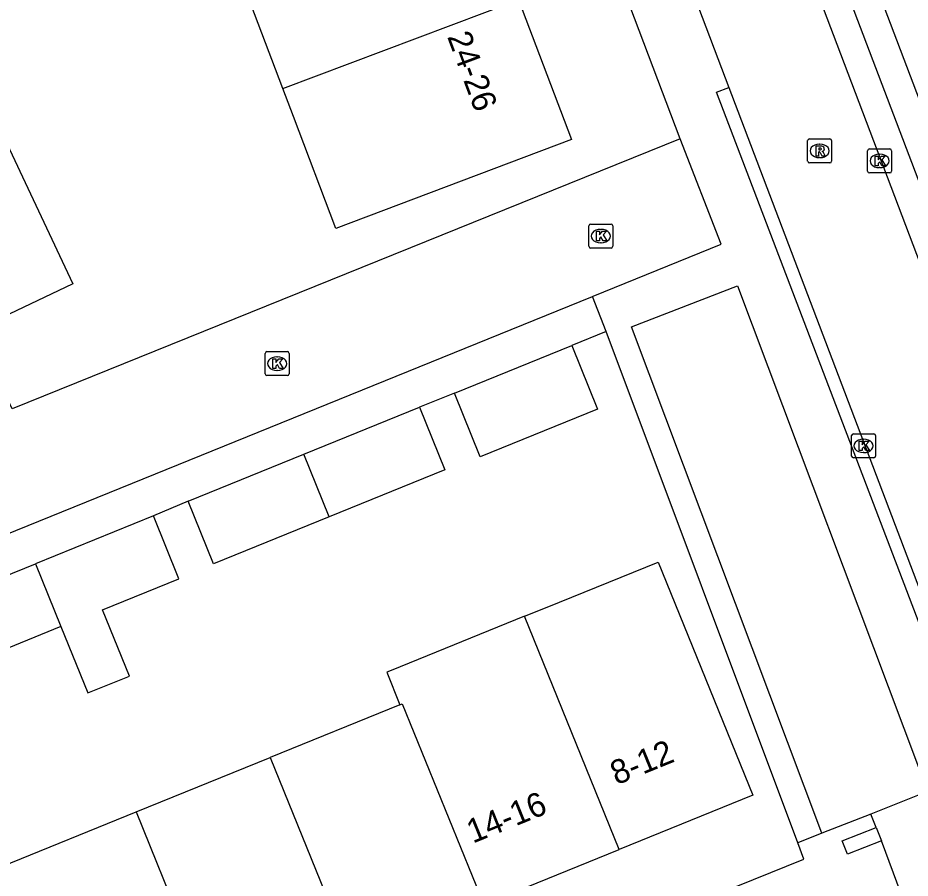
# Model space of a CAD drawing. Extents: x 162990 to 165007, y 383433 to 384336.
# Drawn here: x 163902.75 to 163939.97, y 384004.56 to 384040.43 of the extents above; entities that cross this region are included whole.
import ezdxf

# ---------------------------------------------------------------- set-up
doc = ezdxf.new("R2010")
doc.units = 0
for name, color, linetype in [('IMGEO_Kolk', 7, 'Continuous'), ('IMGEO_Pand', 7, 'Continuous'), ('IMGEO_Pand_nummerreeks', 7, 'Continuous'), ('IMGEO_Rijbaan_lokaal_open', 7, 'Continuous'), ('IMGEO_Rioolput', 7, 'Continuous'), ('IMGEO_Voetpad_open', 7, 'Continuous')]:
    doc.layers.add(name, color=color, linetype=linetype)

msp = doc.modelspace()

# ---------------------------------------------------------------- linework, layer by layer
at = {"layer": 'IMGEO_Kolk'}
for p, q in [((163938.195, 384034.038), (163938.195, 384034.89)), ((163938.27, 384034.964), (163939.122, 384034.964)), ((163938.683, 384034.744), (163938.708, 384034.744)), ((163939.196, 384034.89), (163939.196, 384034.038)), ((163939.122, 384033.964), (163938.27, 384033.964)), ((163938.706, 384034.184), (163938.681, 384034.184)), ((163926.564, 384030.904), (163926.564, 384031.756)), ((163926.639, 384031.83), (163927.491, 384031.83)), ((163927.565, 384031.756), (163927.565, 384030.904)), ((163927.052, 384031.61), (163927.077, 384031.61)), ((163927.075, 384031.05), (163927.05, 384031.05)), ((163927.491, 384030.83), (163926.639, 384030.83)), ((163913.139, 384026.511), (163913.991, 384026.511)), ((163913.064, 384025.585), (163913.064, 384026.437)), ((163913.552, 384026.291), (163913.577, 384026.291)), ((163914.065, 384026.437), (163914.065, 384025.585)), ((163913.991, 384025.511), (163913.139, 384025.511)), ((163913.575, 384025.731), (163913.55, 384025.731)), ((163937.524, 384022.156), (163937.524, 384023.008)), ((163937.599, 384023.082), (163938.451, 384023.082)), ((163938.012, 384022.862), (163938.037, 384022.862)), ((163938.525, 384023.008), (163938.525, 384022.156)), ((163938.451, 384022.082), (163937.599, 384022.082)), ((163938.035, 384022.302), (163938.01, 384022.302))]:
    msp.add_line(p, q, dxfattribs=at)
for points in [[(163938.195, 384034.038), (163938.195, 384034.89)], [(163938.27, 384034.964), (163939.122, 384034.964)], [(163939.196, 384034.89), (163939.196, 384034.038)], [(163938.516, 384034.664), (163938.639, 384034.664), (163938.639, 384034.513), (163938.769, 384034.664), (163938.933, 384034.664), (163938.787, 384034.513), (163938.94, 384034.264), (163938.788, 384034.264), (163938.703, 384034.428), (163938.639, 384034.361), (163938.639, 384034.264), (163938.516, 384034.264), (163938.516, 384034.664)], [(163939.122, 384033.964), (163938.27, 384033.964)], [(163926.564, 384030.904), (163926.564, 384031.756)], [(163926.639, 384031.83), (163927.491, 384031.83)], [(163927.565, 384031.756), (163927.565, 384030.904)], [(163926.885, 384031.53), (163927.008, 384031.53), (163927.008, 384031.379), (163927.138, 384031.53), (163927.302, 384031.53), (163927.156, 384031.379), (163927.309, 384031.13), (163927.157, 384031.13), (163927.072, 384031.294), (163927.008, 384031.227), (163927.008, 384031.13), (163926.885, 384031.13), (163926.885, 384031.53)], [(163927.491, 384030.83), (163926.639, 384030.83)], [(163913.139, 384026.511), (163913.991, 384026.511)], [(163913.064, 384025.585), (163913.064, 384026.437)], [(163913.385, 384026.211), (163913.508, 384026.211), (163913.508, 384026.06), (163913.638, 384026.211), (163913.802, 384026.211), (163913.656, 384026.06), (163913.809, 384025.811), (163913.657, 384025.811), (163913.572, 384025.975), (163913.508, 384025.908), (163913.508, 384025.811), (163913.385, 384025.811), (163913.385, 384026.211)], [(163914.065, 384026.437), (163914.065, 384025.585)], [(163913.991, 384025.511), (163913.139, 384025.511)], [(163937.524, 384022.156), (163937.524, 384023.008)], [(163937.599, 384023.082), (163938.451, 384023.082)], [(163937.845, 384022.782), (163937.968, 384022.782), (163937.968, 384022.631), (163938.098, 384022.782), (163938.262, 384022.782), (163938.116, 384022.631), (163938.269, 384022.382), (163938.117, 384022.382), (163938.032, 384022.546), (163937.968, 384022.479), (163937.968, 384022.382), (163937.845, 384022.382), (163937.845, 384022.782)], [(163938.525, 384023.008), (163938.525, 384022.156)], [(163938.451, 384022.082), (163937.599, 384022.082)]]:
    msp.add_lwpolyline(points, dxfattribs=at)
for centre, start, end in [((163938.272, 384034.888), 91.552, 178.448), ((163938.272, 384034.888), 91.552, 178.448), ((163939.12, 384034.888), 1.552, 88.448), ((163939.12, 384034.888), 1.552, 88.448), ((163938.272, 384034.04), 181.552, 268.448), ((163938.272, 384034.04), 181.552, 268.448), ((163939.12, 384034.04), 271.552, 358.448), ((163939.12, 384034.04), 271.552, 358.448), ((163926.641, 384031.754), 91.552, 178.448), ((163926.641, 384031.754), 91.552, 178.448), ((163927.489, 384031.754), 1.552, 88.448), ((163927.489, 384031.754), 1.552, 88.448), ((163926.641, 384030.906), 181.552, 268.448), ((163926.641, 384030.906), 181.552, 268.448), ((163927.489, 384030.906), 271.552, 358.448), ((163927.489, 384030.906), 271.552, 358.448), ((163913.141, 384026.435), 91.552, 178.448), ((163913.141, 384026.435), 91.552, 178.448), ((163913.989, 384026.435), 1.552, 88.448), ((163913.989, 384026.435), 1.552, 88.448), ((163913.141, 384025.587), 181.552, 268.448), ((163913.141, 384025.587), 181.552, 268.448), ((163913.989, 384025.587), 271.552, 358.448), ((163913.989, 384025.587), 271.552, 358.448), ((163937.601, 384023.006), 91.552, 178.448), ((163937.601, 384023.006), 91.552, 178.448), ((163938.449, 384023.006), 1.552, 88.448), ((163938.449, 384023.006), 1.552, 88.448), ((163937.601, 384022.158), 181.552, 268.448), ((163937.601, 384022.158), 181.552, 268.448), ((163938.449, 384022.158), 271.552, 358.448), ((163938.449, 384022.158), 271.552, 358.448)]:
    msp.add_arc(centre, 0.0765, start, end, dxfattribs=at)
for centre, major_axis, ratio, start_param, end_param in [((163938.682, 384034.464), (-0.387, 0.002), 0.722429, 4.712389, 7.853982), ((163938.707, 384034.464), (-0.39, 0.002), 0.717154, 1.570796, 4.712389), ((163927.051, 384031.33), (-0.387, 0.002), 0.722429, 4.712389, 7.853982), ((163927.076, 384031.33), (-0.39, 0.002), 0.717154, 1.570796, 4.712389), ((163913.551, 384026.011), (-0.387, 0.002), 0.722429, 4.712389, 7.853982), ((163913.576, 384026.011), (-0.39, 0.002), 0.717154, 1.570796, 4.712389), ((163938.011, 384022.582), (-0.387, 0.002), 0.722429, 4.712389, 7.853982), ((163938.036, 384022.582), (-0.39, 0.002), 0.717154, 1.570796, 4.712389)]:
    msp.add_ellipse(centre, major_axis=major_axis, ratio=ratio, start_param=start_param, end_param=end_param, dxfattribs=at)
at = {"layer": 'IMGEO_Pand'}
for points in [[(163913.8, 384037.482), (163911.591, 384043.32)], [(163913.8, 384037.482), (163923.627, 384041.2)], [(163923.627, 384041.2), (163925.836, 384035.362), (163916.01, 384031.643), (163914.24, 384036.32), (163913.8, 384037.482)], [(163897.85, 384037.688), (163900.51, 384038.942), (163905.043, 384029.332), (163902.383, 384028.078), (163897.85, 384037.688)], [(163920.957, 384024.777), (163925.849, 384026.763)], [(163925.849, 384026.763), (163926.926, 384024.111), (163922.034, 384022.124), (163920.957, 384024.777)], [(163914.679, 384022.23), (163919.506, 384024.19)], [(163919.506, 384024.19), (163920.565, 384021.579), (163915.736, 384019.618)], [(163909.854, 384020.271), (163914.679, 384022.23)], [(163915.736, 384019.618), (163914.679, 384022.23)], [(163915.736, 384019.618), (163910.914, 384017.661), (163909.854, 384020.271)], [(163908.4, 384019.665), (163903.482, 384017.669)], [(163904.546, 384015.044), (163905.667, 384012.278), (163907.403, 384012.982), (163906.282, 384015.749), (163909.465, 384017.041), (163908.4, 384019.665)], [(163898.746, 384015.746), (163903.482, 384017.669)], [(163903.482, 384017.669), (163904.546, 384015.044)], [(163923.886, 384015.476), (163924.829, 384015.859), (163929.461, 384017.739), (163933.408, 384008.018), (163927.834, 384005.754)], [(163904.546, 384015.044), (163899.811, 384013.122), (163898.746, 384015.746)], [(163923.886, 384015.476), (163918.325, 384013.218), (163918.138, 384013.142), (163918.687, 384011.79)], [(163927.834, 384005.754), (163923.886, 384015.476)], [(163918.687, 384011.79), (163913.273, 384009.592)], [(163918.687, 384011.79), (163918.781, 384011.828), (163922.182, 384003.459), (163922.26, 384003.491)], [(163907.678, 384007.32), (163913.273, 384009.592)], [(163913.273, 384009.592), (163917.262, 383999.755)], [(163902.084, 384005.049), (163907.678, 384007.32)], [(163907.678, 384007.32), (163911.665, 383997.486)], [(163922.26, 384003.491), (163927.834, 384005.754)]]:
    msp.add_lwpolyline(points, dxfattribs=at)
at = {"layer": 'IMGEO_Rijbaan_lokaal_open'}
for points in [[(163909.453, 384098.047), (163932.403, 384037.527)], [(163928.089, 384062.572), (163943.363, 384022.339)], [(163932.403, 384037.527), (163941.155, 384014.522)], [(163930.377, 384035.386), (163902.507, 384024.128), (163901.478, 384026.314)], [(163926.713, 384028.812), (163926.74, 384028.823), (163932.083, 384030.999), (163930.377, 384035.386)], [(163883.455, 384011.268), (163926.713, 384028.812)]]:
    msp.add_lwpolyline(points, dxfattribs=at)
at = {"layer": 'IMGEO_Rioolput'}
for p, q in [((163935.693, 384034.456), (163935.693, 384035.308)), ((163935.768, 384035.382), (163936.62, 384035.382)), ((163936.181, 384035.162), (163936.206, 384035.162)), ((163936.694, 384035.308), (163936.694, 384034.456)), ((163936.62, 384034.382), (163935.768, 384034.382)), ((163936.204, 384034.602), (163936.179, 384034.602))]:
    msp.add_line(p, q, dxfattribs=at)
for points in [[(163935.693, 384034.456), (163935.693, 384035.308)], [(163935.768, 384035.382), (163936.62, 384035.382)], [(163936.282, 384035.08), (163936.03, 384035.082), (163936.03, 384034.682)], [(163936.694, 384035.308), (163936.694, 384034.456)], [(163936.03, 384034.682), (163936.154, 384034.682), (163936.154, 384034.844), (163936.165, 384034.844)], [(163936.208, 384035.001), (163936.154, 384035.001), (163936.154, 384034.92)], [(163936.154, 384034.92), (163936.206, 384034.92)], [(163936.212, 384034.815), (163936.283, 384034.682), (163936.423, 384034.682), (163936.358, 384034.808)], [(163936.62, 384034.382), (163935.768, 384034.382)]]:
    msp.add_lwpolyline(points, dxfattribs=at)
for centre, radius, start, end in [((163935.77, 384035.306), 0.0765, 91.552, 178.448), ((163935.77, 384035.306), 0.0765, 91.552, 178.448), ((163936.281, 384034.97), 0.109, 350.3612, 89.416), ((163936.618, 384035.306), 0.0765, 1.552, 88.448), ((163936.618, 384035.306), 0.0765, 1.552, 88.448), ((163936.164, 384034.791), 0.0533, 26.0293, 88.6989), ((163936.19, 384035.109), 0.19, 274.7715, 282.9687), ((163936.214, 384034.905), 0.0964, 77.0061, 93.1865), ((163936.228, 384034.962), 0.0378, 276.6634, 79.6772), ((163936.279, 384034.97), 0.112, 277.5842, 350.9817), ((163936.263, 384034.755), 0.108, 29.5134, 73.7905), ((163935.77, 384034.458), 0.0765, 181.552, 268.448), ((163935.77, 384034.458), 0.0765, 181.552, 268.448), ((163936.618, 384034.458), 0.0765, 271.552, 358.448), ((163936.618, 384034.458), 0.0765, 271.552, 358.448)]:
    msp.add_arc(centre, radius, start, end, dxfattribs=at)
for centre, major_axis, ratio, start_param, end_param in [((163936.18, 384034.882), (-0.387, 0.002), 0.722429, 4.712389, 7.853982), ((163936.205, 384034.882), (-0.39, 0.002), 0.717154, 1.570796, 4.712389)]:
    msp.add_ellipse(centre, major_axis=major_axis, ratio=ratio, start_param=start_param, end_param=end_param, dxfattribs=at)
at = {"layer": 'IMGEO_Voetpad_open'}
for points in [[(163947.541, 384018.062), (163947.096, 384019.256), (163932.033, 384058.943), (163917.32, 384097.768), (163911.891, 384112.19)], [(163928.089, 384062.572), (163929.171, 384062.968), (163944.456, 384022.755), (163943.363, 384022.339)], [(163930.377, 384035.386), (163923.18, 384054.38)], [(163943.847, 384007.446), (163943.376, 384007.266), (163942.325, 384010.017), (163931.891, 384037.332), (163932.403, 384037.527)], [(163936.28, 384006.427), (163928.351, 384027.544), (163932.772, 384029.248), (163940.314, 384009.185), (163940.698, 384008.164), (163938.328, 384007.232)], [(163927.294, 384027.344), (163926.713, 384028.812)], [(163927.294, 384027.344), (163925.849, 384026.763)], [(163935.283, 384006.035), (163927.294, 384027.344)], [(163920.957, 384024.777), (163919.506, 384024.19)], [(163909.854, 384020.271), (163908.4, 384019.665)], [(163938.328, 384007.232), (163936.28, 384006.427)], [(163938.547, 384006.674), (163938.328, 384007.232)], [(163936.28, 384006.427), (163935.283, 384006.035)], [(163938.767, 384006.115), (163937.352, 384005.559), (163937.132, 384006.117), (163938.547, 384006.674)], [(163938.547, 384006.674), (163938.767, 384006.115)], [(163860.657, 383975.132), (163922.286, 384000), (163935.54, 384005.348), (163935.283, 384006.035)], [(163939.919, 384003.04), (163938.767, 384006.115)]]:
    msp.add_lwpolyline(points, dxfattribs=at)

# ---------------------------------------------------------------- texts
at = {"layer": 'IMGEO_Pand_nummerreeks'}
for s, rotation, p in [('24-26', 290.4099, (163920.647, 384039.648)), ('8-12', 22.1056, (163927.719, 384008.427)), ('14-16', 22.099, (163921.724, 384005.993))]:
    msp.add_text(s, height=1, rotation=rotation, dxfattribs=at).set_placement(p)

doc.saveas('drawing.dxf')
